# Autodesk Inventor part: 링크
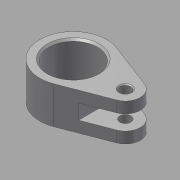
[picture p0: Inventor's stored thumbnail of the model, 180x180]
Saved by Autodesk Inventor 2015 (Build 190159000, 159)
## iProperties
Created: 2015-12
Part Number: 링크
Material: 강철, 연강
Document SubType Name: Modeling
Designer: mduedu
Density: 7.86 g/cm^3
Appearance: 강철
Author: mduedu
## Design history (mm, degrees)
sketch "스케치1"
  geometry: L1 (6.429, -16.813)-(30.857, -7.472); L2 (6.429, 16.813)-(30.857, 7.472); A1 r 18 centre (0, 0) between (6.429, 16.813) and (6.429, -16.813); A2 r 8 centre (28, 0) between (30.857, -7.472) and (30.857, 7.472); 1 further point
  constraints: 4 end point, 4 point on circle, 4 tangent, 2 centre point, 1 coincident, 1 horizontal alignment
  dimensions: "d0" = 18 radius of A1; "d1" = 8 radius of A2; "d2" = 28 distance of A2.centre point (0, 0)
extrude "돌출1" new body sketch "스케치1" stored distance "d3" = 20; taper "d4" = 0 deg
sketch "스케치2"
  geometry: L1 (6.429, 16.813)-(30.857, 7.472) reference; L2 (30.857, -7.472)-(6.429, -16.813) reference; L3 (16, 13.153)-(16, -13.153); A1 r 8 centre (28, 0) between (30.857, -7.472) and (30.857, 7.472) reference; 1 further point
  constraints: 2 end point, 2 point on line, 1 vertical
  dimensions: "d5" = 20 dimension on A1 L3
extrude "돌출2" cut sketch "스케치2" stored distance "d6" = 8; taper "d7" = 0 deg
hole "구멍1" diameter "d10" = 26; stored, may be unused: countersink angle "d14" = 90 deg, drill point angle "d16" = 118 deg; dims "d8" = 10, "d9" = 10, "d11" = 6, "d12" = 4, "d13" = 2, "d15" = 8
hole "구멍2" diameter "d19" = 6; stored, may be unused: countersink angle "d23" = 90 deg, drill point angle "d25" = 118 deg; dims "d20" = 6, "d21" = 4, "d22" = 2, "d24" = 8, "d32" = 10, "d33" = 10
chamfer "모따기1" distance "d26" = 1; stored, may be unused: second distance "d27" = 2, angle "d28" = 45 deg
chamfer "모따기2" distance "d29" = 0.5; stored, may be unused: second distance "d30" = 2, angle "d31" = 45 deg
node "솔리드1"
